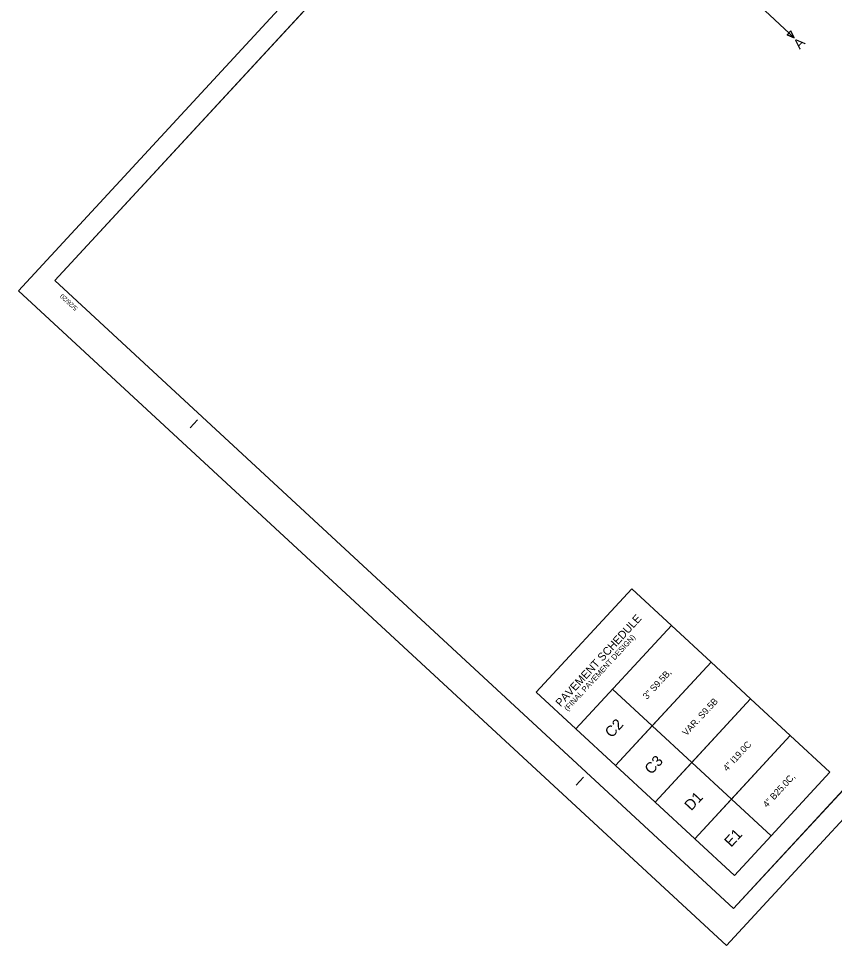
# Model space of a CAD drawing. Extents: x 1768274 to 1769121, y 999922 to 1000687.
# Drawn here: x 1768729 to 1768915.3, y 999922 to 1000133.4 of the extents above; entities that cross this region are included whole.
import ezdxf

# ---------------------------------------------------------------- set-up
doc = ezdxf.new("R2010")
doc.units = 0
for name, color, linetype in [('E_NCDOT_Terrain_Model_Contour_Imported', 7, 'Continuous'), ('E_NCDOT_Terrain_Model_Contour_Major', 7, 'Continuous'), ('E_NCDOT_Terrain_Model_Spot_Elevation', 7, 'Continuous'), ('E_NCDOT_Terrain_Model_Triangles', 7, 'Continuous')]:
    doc.layers.add(name, color=color, linetype=linetype)

msp = doc.modelspace()

# ---------------------------------------------------------------- linework, layer by layer
at = {"layer": 'E_NCDOT_Terrain_Model_Contour_Imported'}
msp.add_lwpolyline([(1768737.29, 1000073.61), (1768947.71, 1000301.25), (1769102.65, 1000158.03), (1768892.23, 999930.38)], close=True, dxfattribs=at)
at = {"layer": 'E_NCDOT_Terrain_Model_Contour_Major'}
for p, q in [((1768961.29, 1000315.94), (1768737.29, 1000073.61)), ((1768892.23, 999930.38), (1769116.23, 1000172.72)), ((1768892.23, 999930.38), (1768737.29, 1000073.61)), ((1768768.19, 1000040.01), (1768769.89, 1000041.85)), ((1768856.31, 999958.56), (1768858.01, 999960.39)), ((1768896.3, 999934.79), (1768896.3, 999934.79))]:
    msp.add_line(p, q, dxfattribs=at)
at = {"layer": 'E_NCDOT_Terrain_Model_Spot_Elevation'}
msp.add_lwpolyline([(1768729.03, 1000071.31), (1768959.82, 1000320.98), (1769121.37, 1000171.65), (1768890.59, 999921.97)], close=True, dxfattribs=at)
at = {"layer": 'E_NCDOT_Terrain_Model_Triangles'}
for p, q in [((1768898.33, 1000136.18), (1768906.08, 1000129.01)), ((1768904.45, 1000129.68), (1768905.29, 1000130.59)), ((1768906.08, 1000129.01), (1768905.29, 1000130.59)), ((1768906.08, 1000129.01), (1768904.45, 1000129.68)), ((1768890.59, 999921.97), (1768890.59, 999921.97))]:
    msp.add_line(p, q, dxfattribs=at)
for points in [[(1768904.45, 1000129.68), (1768906.08, 1000129.01), (1768905.29, 1000130.59)], [(1768847.21, 999979.75), (1768868.99, 1000003.31), (1768878.03, 999994.95), (1768856.25, 999971.39)]]:
    msp.add_lwpolyline(points, close=True, dxfattribs=at)
for points in [[(1768873.65, 999972.07), (1768865.29, 999963.03), (1768856.25, 999971.39), (1768878.03, 999994.95), (1768887.08, 999986.6), (1768873.65, 999972.07), (1768864.61, 999980.43)], [(1768882.69, 999963.71), (1768874.33, 999954.67), (1768865.29, 999963.03), (1768887.08, 999986.6), (1768896.12, 999978.24), (1768882.69, 999963.71), (1768873.65, 999972.07)], [(1768891.73, 999955.36), (1768883.37, 999946.32), (1768874.33, 999954.67), (1768896.12, 999978.24), (1768905.16, 999969.88), (1768891.73, 999955.36), (1768882.69, 999963.71)], [(1768900.77, 999947), (1768892.42, 999937.96), (1768883.37, 999946.32), (1768905.16, 999969.88), (1768914.2, 999961.52), (1768900.77, 999947), (1768891.73, 999955.36)]]:
    msp.add_lwpolyline(points, dxfattribs=at)

# ---------------------------------------------------------------- texts
at = {"layer": 'E_NCDOT_Terrain_Model_Contour_Major'}
msp.add_text('5/26/20', height=1.05, rotation=137.2512, dxfattribs=at).set_placement((1768742.64, 1000067.39))
at = {"layer": 'E_NCDOT_Terrain_Model_Triangles'}
for s, height, p in [('A', 2.27, (1768907.34, 1000126.25)), ('PAVEMENT SCHEDULE', 1.8256, (1768852.75, 999976.3)), ('(FINAL PAVEMENT DESIGN)', 1.2418, (1768854.34, 999975.33)), ('3" S9.5B, ', 1.505, (1768872.46, 999977.98)), (' VAR. S9.5B', 1.5048, (1768881.12, 999969.25)), ('C2', 2.458, (1768864.41, 999969.17)), ('4" I19.0C', 1.505, (1768890.76, 999961.6)), ('C3', 2.458, (1768873.46, 999960.82)), ('4" B25.0C,', 1.505, (1768899.85, 999953.3)), ('D1', 2.458, (1768882.57, 999952.54)), ('E1', 2.458, (1768891.67, 999944.25))]:
    msp.add_text(s, height=height, rotation=47.2512, dxfattribs=at).set_placement(p)

doc.saveas('drawing.dxf')
